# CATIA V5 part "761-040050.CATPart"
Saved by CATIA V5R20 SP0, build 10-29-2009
Part number: 761-040050
Source: Unknown
Property "ARTICLENO": "761-040050"
Property "BOMINFO": "761-040050"
Property "CODE": "761-040050"
Property "H": "40.000"
Property "L1": "50.000"
Property "L2": "32.000"
Property "LINA": "761-040050"
Property "NB": "761-040050"
Property "NBSYN": "$CODE."
Property "NN": "761"
Property "NT": "VW/AUDI Keys"
Property "P": "4.000"
Property "SUPPLIER": "CF"
Bounding box of the stored display mesh (mm): x -25 to 25, y 0 to 40, z -11 to 11
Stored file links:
  C:\Users\Utente\Desktop\3D files 761\761-040050.CATPart
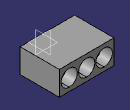
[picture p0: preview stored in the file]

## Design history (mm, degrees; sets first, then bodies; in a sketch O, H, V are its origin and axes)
Body1 "Geometry.1" (main body)
  Solid1 "761-040050.catpart": solid without history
